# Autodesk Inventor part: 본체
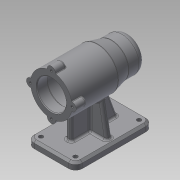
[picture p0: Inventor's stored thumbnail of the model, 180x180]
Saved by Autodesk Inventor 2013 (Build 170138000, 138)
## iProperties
Created: 2019-07
Part Number: 본체
Material: 일반
Document SubType Name: Modeling
Designer: Administrator
Density: 1 g/cm^3
Author: Administrator
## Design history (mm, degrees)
sketch "스케치1"
  geometry: L1 (0, 0)-(-112, 0); L2 (0, 0)-(0, 30); L3 (0, 30)-(-67, 30); L4 (-67, 30)-(-87, 25); L5 (-87, 25)-(-112, 25); L6 (-112, 25)-(-112, 0); L7 (0, 21)-(-15, 21); L8 (-15, 24)-(-69, 24); L9 (-69, 24)-(-69, 21); L10 (-69, 21)-(-81, 21); L11 (-81, 21)-(-81, 17.5); L12 (-81, 17.5)-(-99, 17.5); L13 (-99, 17.5)-(-99, 16); L14 (-99, 16)-(-103, 16); L15 (-15, 21)-(-15, 24); L16 (-103, 16)-(-103, 10.5); L17 (-103, 10.5)-(-106, 10.5); L18 (-106, 10.5)-(-106, 0); 1 further point
  constraints: 36 end point, 9 horizontal, 8 vertical, 2 point on line, 1 coincident
  dimensions: "d0" = 112 distance of L1.start L1.end; "d2" = 50 diameter of L5 L1; "d3" = 60 diameter of L3 L1; "d4" = 25 distance of L4.end L5.end; "d5" = 45 distance from line of L6 L3.end; "d6" = 42 diameter of L7 L1; "d7" = 48 diameter of L8 L1; "d8" = 42 diameter of L10 L1; "d9" = 35 diameter of L12 L1; "d10" = 32 diameter of L14 L1; "d11" = 21 diameter of L17 L1; "d12" = 3 distance of L16.end L17.end; "d13" = 4 distance of L13.end L14.end; "d14" = 18 distance of L11.end L12.end; "d15" = 12 distance of L9.end L10.end; "d16" = 54 distance of L8.start L8.end; "d17" = 15 distance of L7.start L7.end
revolve "회전1" sketch "스케치1" stored, may be unused: angle "d18" = 90 deg
fillet "모깎기1" dims "d19" = 10
sketch "스케치2"
  geometry: C1 r 21 at (0, 0) reference; C2 r 6 at (30, 0); 1 further point
  constraints: 2 horizontal alignment, 1 centre point, 1 other
  dimensions: "d20" = 12 diameter of C2
extrude "돌출1" join sketch "스케치2" distance "d23" = 16; taper "d24" = 0 deg
hole "구멍1" diameter "d27" = 3.242; stored, may be unused: countersink angle "d31" = 90 deg, drill point angle "d33" = 118 deg; dims "d25" = 10, "d26" = 10, "d28" = 8, "d29" = 4, "d30" = 2, "d32" = 11
node "작업 평면1"
sketch "스케치3"
  geometry: L1 (0, 0)-(56, 0); L2 (56, 0)-(56, -35); L3 (56, -35)-(112, -35); L4 (112, -35)-(112, 35); L5 (112, 35)-(0, 35); L6 (0, 35)-(0, -35); L7 (0, -35)-(56, -35)
  constraints: 14 end point, 3 horizontal, 3 vertical
  dimensions: "d38" = 56 distance of L1.start L1.end; "d39" = 35 distance of L1.end L2.end; "d40" = 56 distance of L2.end L3.end; "d41" = 70 distance of L3.end L4.end; "d42" = 112 distance of L4.end L5.end; "d43" = 70 distance of L5.end L6.end
extrude "돌출2" join sketch "스케치3" distance "d44" = 10; taper "d45" = 0 deg
fillet "모깎기2" dims "d46" = 10
sketch "스케치4"
  geometry: C1 r 3 at (-102, 25); C2 r 3 at (-102, -25); C3 r 3 at (-10, -25); C4 r 3 at (-10, 25); A1 r 10 centre (-102, -25) between (-112, -25) and (-102, -35) reference; A2 r 10 centre (-10, -25) between (-10, -35) and (0, -25) reference; A3 r 10 centre (-10, 25) between (0, 25) and (-10, 35) reference; A4 r 10 centre (-102, 25) between (-102, 35) and (-112, 25) reference; 1 further point
  constraints: 4 centre point, 4 coincident, 3 equal radius
  dimensions: "d47" = 6 diameter of C1
extrude "돌출3" cut sketch "스케치4" stored distance "d49" = 10; taper "d50" = 0 deg
sketch "스케치5"
  geometry: L1 (0, -25)-(0, 25) reference; L2 (-112, 25)-(-112, -25) reference; L3 (-25, -4)-(-92, -4); L4 (-92, -4)-(-92, 4); L5 (-92, 4)-(-25, 4); L6 (-25, 4)-(-25, -4); L7 (-25, -4)-(-92, 4); L8 (-92, -4)-(-25, 4); 4 further points
  constraints: 12 end point, 4 midpoint, 2 parallel, 1 horizontal, 1 horizontal alignment, 1 perpendicular
  dimensions: "d54" = 25 distance between parallel lines of L1 L6; "d55" = 20 distance between parallel lines of L2 L4; "d56" = 8 distance of L3.end L4.end
extrude "돌출4" join sketch "스케치5" stored distance "d57" = 10; taper "d58" = 0 deg
feature "면 기울기1" dims angle "d59" = 20 deg
node "작업 평면2"
sketch "스케치6"
  geometry: L1 (-70, -25)-(-70, 25) reference; L2 (-70, -28)-(-41.732, -23.016); L3 (-70, -35)-(-80, -35) reference; 1 further point
  constraints: 2 end point, 1 point on line
  dimensions: "d61" = 7 distance from line of L3 L2.start; "d62" = 100 deg angle of L1 L2
feature "리브1" sketch "스케치6" dims "d63" = 1, "d64" = 8, "d65" = 0, "d66" = 0, "d67" = 1, "d68" = 1
node "작업 평면3"
sketch "스케치7"
  geometry: L1 (0, 36)-(0, 29.4) reference; 2 further points
  constraints: 1 horizontal alignment, 1 other
  dimensions: "d86" = 42 distance from line of point (-42, 0) L1
feature "엠보싱1" sketch "스케치7" dims "d0" = 112, "d2" = 50, "d3" = 60, "d4" = 25, "d5" = 45, "d6" = 42, "d7" = 48, "d8" = 42, "d9" = 35, "d10" = 32, "d11" = 21, "d12" = 3, "d13" = 4, "d14" = 18, "d15" = 12, "d16" = 54, "d17" = 15, "d71" = 0.5, "d72" = 0
fillet "모깎기3" dims "d73" = 3
fillet "모깎기4" dims "d74" = 1
fillet "모깎기6" dims "d76" = 3
fillet "모깎기12" dims "d83" = 3
fillet "모깎기13" dims "d84" = 3
fillet "모깎기14" dims "d85" = 3, "d87" = 0.3
chamfer "모따기1" distance "d88" = 3; stored, may be unused: second distance "d89" = 2, angle "d90" = 45 deg
fillet "모깎기15" dims "d91" = 3
chamfer "모따기2" distance "d92" = 1; stored, may be unused: second distance "d93" = 2, angle "d94" = 45 deg
node "솔리드1"
pattern_circular "원형 패턴1" dims angle "d35" = 360 deg
mirror "대칭1"
other parameters: "d60" = -56
